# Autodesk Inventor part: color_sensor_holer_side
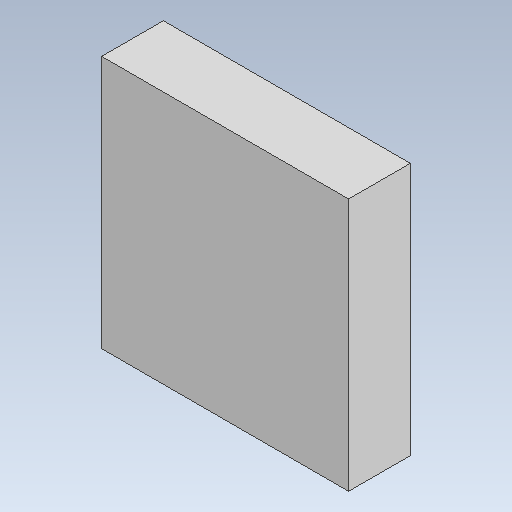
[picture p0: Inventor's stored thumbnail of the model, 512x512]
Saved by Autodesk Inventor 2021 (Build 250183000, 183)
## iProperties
Created: 2026-10
Part Number: color_sensor_holer_side
Material: Generic
Document SubType Name: Modeling
Designer: alolo
Density: 1 g/cm^3
Appearance: Default
Author: alolo
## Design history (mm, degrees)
sketch "Sketch1"
  geometry: L1 (0, 0)-(20, 0); L2 (20, 0)-(20, 20.5); L3 (20, 20.5)-(0, 20.5); L4 (0, 20.5)-(0, 0)
  constraints: 8 end point, 2 parallel, 1 horizontal, 1 perpendicular
  dimensions: "d0" = 20 distance of L3.end L2.end; "d1" = 20.5 distance of L2.end L1.end
extrude "Extrusion1" new body sketch "Sketch1" distance "d2" = 5 (= wood_thickness); taper "d3" = 0 deg
body "Solid1"
other parameters: "slide_length" = 195 [user parameter], "slide_angle" = 7 deg [user parameter], "slide_width" = 65 [user parameter], "wood_thickness" = 5 [user parameter; used in 1 equation term], "aclyric_thickness" = 6 [user parameter]
